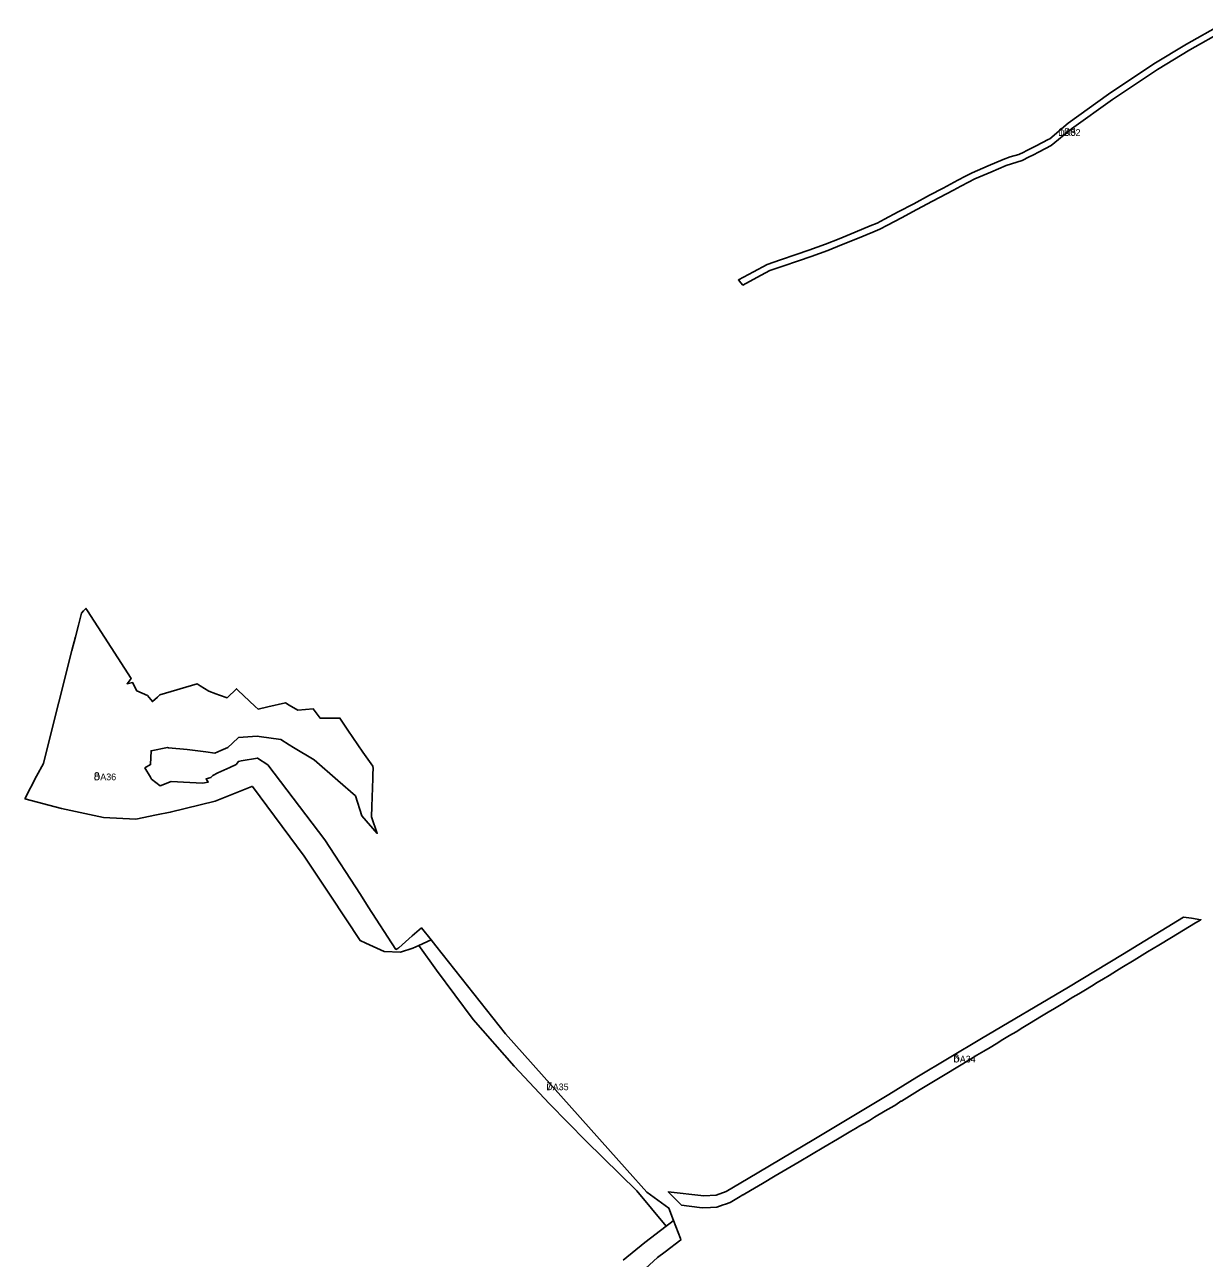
# Model space of a CAD drawing. Extents: x -537012 to -534603, y -1176562 to -1172739.
# Drawn here: x -537012 to -536128, y -1174132 to -1173207 of the extents above; entities that cross this region are included whole.
import ezdxf

# ---------------------------------------------------------------- set-up
doc = ezdxf.new("R2010")
doc.units = 0
doc.layers.add('96140023', color=7, linetype='Continuous')
doc.layers.add('ID_VPO', color=7, linetype='Continuous')

msp = doc.modelspace()

# ---------------------------------------------------------------- linework, layer by layer
at = {"layer": '96140023'}
for points in [[(-536113.11, -1173211.09), (-536138.71, -1173225.54), (-536163.03, -1173240.21), (-536196.76, -1173262.83), (-536227.35, -1173284.86), (-536242.63, -1173297.35), (-536251.72, -1173302.02), (-536256.57, -1173304.51), (-536259.11, -1173305.81), (-536264.58, -1173308.62), (-536276.53, -1173312.23), (-536287.98, -1173317.17), (-536299.84, -1173322.28), (-536304.64, -1173324.81), (-536310.37, -1173327.83), (-536315.87, -1173330.73), (-536321.29, -1173333.59), (-536331.65, -1173339.06), (-536343.44, -1173345.34), (-536355.02, -1173351.51), (-536365.31, -1173356.99), (-536371.16, -1173360.1), (-536376.47, -1173362.27), (-536387.87, -1173366.92), (-536399.85, -1173371.81), (-536410.04, -1173375.97), (-536422.65, -1173380.48), (-536432.27, -1173383.77), (-536443.98, -1173387.77), (-536453.72, -1173391.1), (-536463.51, -1173396.36), (-536473.84, -1173401.92), (-536475.27, -1173400.29), (-536477.22, -1173398.07), (-536465.88, -1173391.96), (-536455.73, -1173386.5), (-536445.6, -1173383.04), (-536433.89, -1173379.04), (-536424.3, -1173375.76), (-536411.83, -1173371.3), (-536401.74, -1173367.18), (-536389.76, -1173362.29), (-536378.36, -1173357.64), (-536373.28, -1173355.57), (-536367.66, -1173352.58), (-536357.37, -1173347.1), (-536345.79, -1173340.93), (-536333.99, -1173334.64), (-536323.62, -1173329.17), (-536318.2, -1173326.31), (-536312.7, -1173323.41), (-536306.97, -1173320.39), (-536302, -1173317.77), (-536289.96, -1173312.58), (-536278.74, -1173307.74), (-536273.57, -1173305.71), (-536266.86, -1173304.17), (-536263.18, -1173302.28), (-536261.39, -1173301.36), (-536258.85, -1173300.06), (-536256.07, -1173298.63), (-536254, -1173297.57), (-536244.91, -1173292.9), (-536243.78, -1173292.32), (-536230.04, -1173280.63), (-536199.61, -1173258.72), (-536165.72, -1173235.99), (-536141.23, -1173221.22), (-536115.5, -1173206.7)], [(-536563.66, -1174133), (-536547.35, -1174119.82), (-536531.3, -1174107.64), (-536527.4, -1174104.68), (-536525.77, -1174103.45), (-536520.69, -1174116.97), (-536520.35, -1174117.88), (-536532.23, -1174126.8), (-536537.99, -1174131.12), (-536549.77, -1174142.2)]]:
    msp.add_lwpolyline(points, dxfattribs=at)
for points in [[(-537012.32, -1173787.26), (-537003.41, -1173770.23), (-536998.3, -1173760.8), (-536996.52, -1173753.5), (-536976.89, -1173676.04), (-536974.28, -1173665.76), (-536972.08, -1173657.08), (-536969.8, -1173648.07), (-536968.14, -1173646.29), (-536966.39, -1173644.41), (-536965.23, -1173646.2), (-536952.52, -1173665.92), (-536932.53, -1173696.93), (-536935.6, -1173700.95), (-536931.45, -1173700.04), (-536928.11, -1173706.3), (-536920.26, -1173709.8), (-536916.56, -1173714.28), (-536912.74, -1173710.88), (-536910.9, -1173709.24), (-536902.41, -1173706.75), (-536891.59, -1173703.57), (-536882.88, -1173701.01), (-536880.69, -1173702.42), (-536874.31, -1173706.54), (-536868.89, -1173708.43), (-536866.29, -1173709.34), (-536860.56, -1173711.34), (-536853.61, -1173704.66), (-536852.43, -1173705.78), (-536839.52, -1173717.94), (-536837.38, -1173719.95), (-536830.12, -1173718.3), (-536816.89, -1173715.3), (-536814.12, -1173716.89), (-536807.52, -1173720.67), (-536795.97, -1173719.79), (-536790.84, -1173726.67), (-536790.16, -1173726.67), (-536775.96, -1173726.62), (-536774.64, -1173729.06), (-536770.1, -1173735.75), (-536758.9, -1173752.25), (-536751.36, -1173762.78), (-536751.08, -1173764.33), (-536751.23, -1173768.8), (-536751.34, -1173771.89), (-536752.06, -1173792.98), (-536752.33, -1173800.78), (-536748.01, -1173813.08), (-536759.46, -1173799.92), (-536764.31, -1173784.99), (-536777.49, -1173773.43), (-536795.16, -1173757.93), (-536810.75, -1173748.61), (-536813.97, -1173746.6), (-536820.25, -1173742.68), (-536836.39, -1173740.47), (-536837.94, -1173740.26), (-536852, -1173741.16), (-536856.5, -1173745.4), (-536860.1, -1173748.79), (-536865.19, -1173750.93), (-536869.68, -1173752.83), (-536876.38, -1173751.98), (-536890.58, -1173750.19), (-536904.38, -1173748.85), (-536905.17, -1173748.77), (-536917.53, -1173751.18), (-536917.94, -1173761.52), (-536922.12, -1173764.02), (-536917.89, -1173771.05), (-536917.12, -1173772.33), (-536910.62, -1173777.35), (-536902.39, -1173774.23), (-536888.41, -1173774.93), (-536878.89, -1173775.4), (-536874.65, -1173774.65), (-536876.37, -1173772.2), (-536872.8, -1173771.25), (-536871.29, -1173769.67), (-536867.38, -1173767.81), (-536858.57, -1173763.62), (-536853.81, -1173761.35), (-536852.1, -1173759.16), (-536849.97, -1173758.79), (-536837.77, -1173756.69), (-536830.09, -1173761.6), (-536787.3, -1173817.89), (-536760.66, -1173859.02), (-536754.68, -1173868.25), (-536734.01, -1173900.15), (-536732.55, -1173899.32), (-536732, -1173899), (-536731.89, -1173898.94), (-536721.7, -1173890.01), (-536714.87, -1173884.03), (-536707.68, -1173892.89), (-536716.72, -1173897.04), (-536721.42, -1173899.2), (-536730.59, -1173902.07), (-536742.7, -1173901.73), (-536756.6, -1173895.44), (-536760.91, -1173893.49), (-536782.87, -1173860.22), (-536802.78, -1173830.06), (-536841.57, -1173777.83), (-536842.06, -1173777.98), (-536869.5, -1173788.82), (-536903.14, -1173797.26), (-536913.6, -1173799.22), (-536929.05, -1173802.37), (-536953.24, -1173801.18), (-536984.68, -1173794.53)], [(-536143.4, -1173875.91), (-536137.45, -1173876.78), (-536130.48, -1173877.8), (-536134.51, -1173880.24), (-536143.43, -1173885.65), (-536152.44, -1173891.12), (-536162.02, -1173896.93), (-536170.43, -1173902.03), (-536180.47, -1173908.12), (-536189.66, -1173913.69), (-536193.84, -1173916.22), (-536199.34, -1173919.56), (-536203.54, -1173922.11), (-536208.34, -1173925.02), (-536212.56, -1173927.58), (-536217.1, -1173930.33), (-536221.98, -1173933.29), (-536226.43, -1173935.99), (-536230.5, -1173938.46), (-536230.77, -1173938.62), (-536235.25, -1173941.33), (-536240.18, -1173944.31), (-536245.06, -1173947.26), (-536249.9, -1173950.19), (-536254.51, -1173952.98), (-536258.88, -1173955.62), (-536263.89, -1173958.65), (-536269.08, -1173961.79), (-536273.84, -1173964.67), (-536278.95, -1173967.77), (-536284.02, -1173970.84), (-536288.49, -1173973.54), (-536293.15, -1173976.36), (-536298.34, -1173979.5), (-536303.28, -1173982.49), (-536312.57, -1173988.11), (-536322.18, -1173993.93), (-536340.85, -1174005.23), (-536355, -1174013.79), (-536355.33, -1174014.01), (-536356.37, -1174014.68), (-536358.13, -1174015.83), (-536359.97, -1174017.04), (-536360.3, -1174017.26), (-536360.44, -1174017.34), (-536367.07, -1174021.24), (-536375.12, -1174025.99), (-536378.98, -1174028.27), (-536382.96, -1174030.62), (-536386.11, -1174032.47), (-536389.47, -1174034.45), (-536392.81, -1174036.42), (-536402.81, -1174042.32), (-536413.11, -1174048.39), (-536431.62, -1174059.3), (-536449.69, -1174069.95), (-536459.25, -1174075.58), (-536468.2, -1174080.85), (-536473.56, -1174084.01), (-536473.9, -1174084.21), (-536477.07, -1174086.08), (-536483.39, -1174089.81), (-536486.93, -1174091.07), (-536488.7, -1174091.7), (-536493.33, -1174093.35), (-536498.18, -1174093.56), (-536504.12, -1174093.81), (-536506.47, -1174093.52), (-536519.81, -1174091.88), (-536529.84, -1174081.82), (-536503.22, -1174084.89), (-536494, -1174084.47), (-536486.42, -1174081.59), (-536470.01, -1174071.96), (-536420.7, -1174042.51), (-536364.52, -1174008.91), (-536343.36, -1173995.97), (-536295.01, -1173966.93), (-536229.61, -1173928.51), (-536189.18, -1173903.97)], [(-536531.3, -1174107.64), (-536553.25, -1174081.23), (-536591.39, -1174043.89), (-536618.92, -1174015.95), (-536645.34, -1173987.75), (-536676.1, -1173952.69), (-536703.54, -1173915.67), (-536716.72, -1173897.04), (-536707.68, -1173892.89), (-536704.04, -1173897.38), (-536651.93, -1173963.52), (-536560.66, -1174065.67), (-536545.85, -1174082.18), (-536529.27, -1174094.11), (-536525.77, -1174103.45), (-536527.4, -1174104.68)]]:
    msp.add_lwpolyline(points, close=True, dxfattribs=at)

# ---------------------------------------------------------------- texts
for s, rotation, p in [('DA32', 360, (-536237.47, -1173290.1)), ('DA36', 360, (-536960.46, -1173773.24)), ('DA34', 0, (-536316.03, -1173984.86)), ('DA35', 0, (-536621.24, -1174005.67))]:
    msp.add_text(s, height=5, rotation=rotation, dxfattribs=at).set_placement(p)
at = {"layer": 'ID_VPO'}
for s, rotation, p in [('106', 360, (-536237.47, -1173290.1)), ('8', 360, (-536960.46, -1173773.24)), ('6', 0, (-536316.03, -1173984.86)), ('7', 360, (-536621.24, -1174005.67))]:
    msp.add_text(s, height=6, rotation=rotation, dxfattribs=at).set_placement(p)

doc.saveas('drawing.dxf')
